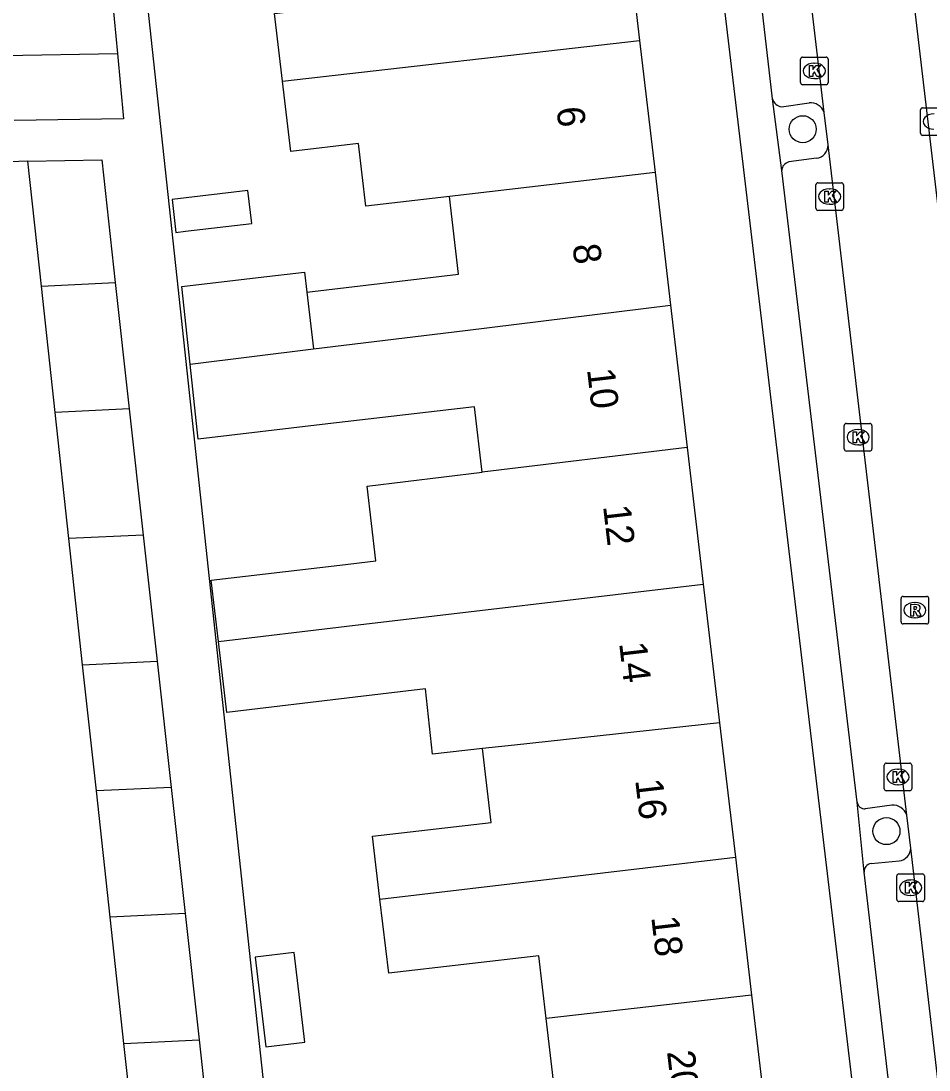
# Model space of a CAD drawing. Extents: x 162250 to 162654, y 380744 to 381605.
# Drawn here: x 162420.44 to 162453.35, y 381062.24 to 381100.24 of the extents above; entities that cross this region are included whole.
import ezdxf

# ---------------------------------------------------------------- set-up
doc = ezdxf.new("R2010")
doc.units = 0
for name, color, linetype in [('IMGEO_Boom', 7, 'Continuous'), ('IMGEO_Kolk', 7, 'Continuous'), ('IMGEO_Pand', 7, 'Continuous'), ('IMGEO_Pand_nummerreeks', 7, 'Continuous'), ('IMGEO_Parkeervlak_open', 7, 'Continuous'), ('IMGEO_Rijbaan_lokaal_open', 7, 'Continuous'), ('IMGEO_Rioolput', 7, 'Continuous'), ('IMGEO_Voetpad_open', 7, 'Continuous')]:
    doc.layers.add(name, color=color, linetype=linetype)

msp = doc.modelspace()

# ---------------------------------------------------------------- linework, layer by layer
at = {"layer": 'IMGEO_Boom'}
for centre in [(162448.769, 381096.32), (162451.803, 381070.891)]:
    msp.add_circle(centre, 0.489, dxfattribs=at)
at = {"layer": 'IMGEO_Kolk'}
for p, q in [((162448.687, 381098.007), (162448.687, 381098.859)), ((162448.762, 381098.933), (162449.614, 381098.933)), ((162449.175, 381098.713), (162449.2, 381098.713)), ((162449.688, 381098.859), (162449.688, 381098.007)), ((162449.614, 381097.933), (162448.762, 381097.933)), ((162449.198, 381098.153), (162449.173, 381098.153)), ((162453.037, 381096.172), (162453.037, 381097.024)), ((162453.112, 381097.098), (162453.964, 381097.098)), ((162453.964, 381096.098), (162453.112, 381096.098)), ((162449.243, 381093.455), (162449.243, 381094.307)), ((162449.318, 381094.381), (162450.17, 381094.381)), ((162449.731, 381094.161), (162449.756, 381094.161)), ((162450.244, 381094.307), (162450.244, 381093.455)), ((162450.17, 381093.381), (162449.318, 381093.381)), ((162449.754, 381093.601), (162449.729, 381093.601)), ((162450.274, 381084.736), (162450.274, 381085.588)), ((162450.349, 381085.662), (162451.201, 381085.662)), ((162450.762, 381085.442), (162450.787, 381085.442)), ((162451.275, 381085.588), (162451.275, 381084.736)), ((162451.201, 381084.662), (162450.349, 381084.662)), ((162450.785, 381084.882), (162450.76, 381084.882)), ((162451.72, 381072.428), (162451.72, 381073.28)), ((162451.795, 381073.354), (162452.647, 381073.354)), ((162452.721, 381073.28), (162452.721, 381072.428)), ((162452.208, 381073.134), (162452.233, 381073.134)), ((162452.231, 381072.574), (162452.206, 381072.574)), ((162452.647, 381072.354), (162451.795, 381072.354)), ((162452.177, 381068.416), (162452.177, 381069.268)), ((162452.252, 381069.342), (162453.104, 381069.342)), ((162452.665, 381069.122), (162452.69, 381069.122)), ((162453.178, 381069.268), (162453.178, 381068.416)), ((162453.104, 381068.342), (162452.252, 381068.342)), ((162452.688, 381068.562), (162452.663, 381068.562))]:
    msp.add_line(p, q, dxfattribs=at)
for points in [[(162448.687, 381098.007), (162448.687, 381098.859)], [(162448.762, 381098.933), (162449.614, 381098.933)], [(162449.688, 381098.859), (162449.688, 381098.007)], [(162449.008, 381098.633), (162449.131, 381098.633), (162449.131, 381098.482), (162449.261, 381098.633), (162449.425, 381098.633), (162449.279, 381098.482), (162449.432, 381098.233), (162449.28, 381098.233), (162449.195, 381098.397), (162449.131, 381098.33), (162449.131, 381098.233), (162449.008, 381098.233), (162449.008, 381098.633)], [(162449.614, 381097.933), (162448.762, 381097.933)], [(162453.037, 381096.172), (162453.037, 381097.024)], [(162453.112, 381097.098), (162453.964, 381097.098)], [(162453.964, 381096.098), (162453.112, 381096.098)], [(162449.243, 381093.455), (162449.243, 381094.307)], [(162449.318, 381094.381), (162450.17, 381094.381)], [(162450.244, 381094.307), (162450.244, 381093.455)], [(162449.564, 381094.081), (162449.687, 381094.081), (162449.687, 381093.93), (162449.817, 381094.081), (162449.981, 381094.081), (162449.835, 381093.93), (162449.988, 381093.681), (162449.836, 381093.681), (162449.751, 381093.845), (162449.687, 381093.778), (162449.687, 381093.681), (162449.564, 381093.681), (162449.564, 381094.081)], [(162450.17, 381093.381), (162449.318, 381093.381)], [(162450.274, 381084.736), (162450.274, 381085.588)], [(162450.349, 381085.662), (162451.201, 381085.662)], [(162450.595, 381085.362), (162450.718, 381085.362), (162450.718, 381085.211), (162450.848, 381085.362), (162451.012, 381085.362), (162450.866, 381085.211), (162451.019, 381084.962), (162450.867, 381084.962), (162450.782, 381085.126), (162450.718, 381085.059), (162450.718, 381084.962), (162450.595, 381084.962), (162450.595, 381085.362)], [(162451.275, 381085.588), (162451.275, 381084.736)], [(162451.201, 381084.662), (162450.349, 381084.662)], [(162451.72, 381072.428), (162451.72, 381073.28)], [(162451.795, 381073.354), (162452.647, 381073.354)], [(162452.721, 381073.28), (162452.721, 381072.428)], [(162452.041, 381073.054), (162452.164, 381073.054), (162452.164, 381072.903), (162452.294, 381073.054), (162452.458, 381073.054), (162452.312, 381072.903), (162452.465, 381072.654), (162452.313, 381072.654), (162452.228, 381072.818), (162452.164, 381072.751), (162452.164, 381072.654), (162452.041, 381072.654), (162452.041, 381073.054)], [(162452.647, 381072.354), (162451.795, 381072.354)], [(162452.177, 381068.416), (162452.177, 381069.268)], [(162452.252, 381069.342), (162453.104, 381069.342)], [(162452.498, 381069.042), (162452.621, 381069.042), (162452.621, 381068.891), (162452.751, 381069.042), (162452.915, 381069.042), (162452.769, 381068.891), (162452.922, 381068.642), (162452.77, 381068.642), (162452.685, 381068.806), (162452.621, 381068.739), (162452.621, 381068.642), (162452.498, 381068.642), (162452.498, 381069.042)], [(162453.178, 381069.268), (162453.178, 381068.416)], [(162453.104, 381068.342), (162452.252, 381068.342)]]:
    msp.add_lwpolyline(points, dxfattribs=at)
for centre, start, end in [((162448.764, 381098.857), 91.552, 178.448), ((162448.764, 381098.857), 91.552, 178.448), ((162449.612, 381098.857), 1.552, 88.448), ((162449.612, 381098.857), 1.552, 88.448), ((162448.764, 381098.009), 181.552, 268.448), ((162448.764, 381098.009), 181.552, 268.448), ((162449.612, 381098.009), 271.552, 358.448), ((162449.612, 381098.009), 271.552, 358.448), ((162453.114, 381097.022), 91.552, 178.448), ((162453.114, 381097.022), 91.552, 178.448), ((162453.114, 381096.174), 181.552, 268.448), ((162453.114, 381096.174), 181.552, 268.448), ((162449.32, 381094.305), 91.552, 178.448), ((162449.32, 381094.305), 91.552, 178.448), ((162450.168, 381094.305), 1.552, 88.448), ((162450.168, 381094.305), 1.552, 88.448), ((162449.32, 381093.457), 181.552, 268.448), ((162449.32, 381093.457), 181.552, 268.448), ((162450.168, 381093.457), 271.552, 358.448), ((162450.168, 381093.457), 271.552, 358.448), ((162450.351, 381085.586), 91.552, 178.448), ((162450.351, 381085.586), 91.552, 178.448), ((162451.199, 381085.586), 1.552, 88.448), ((162451.199, 381085.586), 1.552, 88.448), ((162450.351, 381084.738), 181.552, 268.448), ((162450.351, 381084.738), 181.552, 268.448), ((162451.199, 381084.738), 271.552, 358.448), ((162451.199, 381084.738), 271.552, 358.448), ((162451.797, 381073.278), 91.552, 178.448), ((162451.797, 381073.278), 91.552, 178.448), ((162452.645, 381073.278), 1.552, 88.448), ((162452.645, 381073.278), 1.552, 88.448), ((162451.797, 381072.43), 181.552, 268.448), ((162451.797, 381072.43), 181.552, 268.448), ((162452.645, 381072.43), 271.552, 358.448), ((162452.645, 381072.43), 271.552, 358.448), ((162452.254, 381069.266), 91.552, 178.448), ((162452.254, 381069.266), 91.552, 178.448), ((162453.102, 381069.266), 1.552, 88.448), ((162453.102, 381069.266), 1.552, 88.448), ((162452.254, 381068.418), 181.552, 268.448), ((162452.254, 381068.418), 181.552, 268.448), ((162453.102, 381068.418), 271.552, 358.448), ((162453.102, 381068.418), 271.552, 358.448)]:
    msp.add_arc(centre, 0.0765, start, end, dxfattribs=at)
for centre, major_axis, ratio, start_param, end_param in [((162449.174, 381098.433), (-0.387, 0.002), 0.722429, 4.712389, 7.853982), ((162449.199, 381098.433), (-0.39, 0.002), 0.717154, 1.570796, 4.712389), ((162453.524, 381096.598), (-0.387, 0.002), 0.722429, 4.712389, 7.853982), ((162449.73, 381093.881), (-0.387, 0.002), 0.722429, 4.712389, 7.853982), ((162449.755, 381093.881), (-0.39, 0.002), 0.717154, 1.570796, 4.712389), ((162450.761, 381085.162), (-0.387, 0.002), 0.722429, 4.712389, 7.853982), ((162450.786, 381085.162), (-0.39, 0.002), 0.717154, 1.570796, 4.712389), ((162452.207, 381072.854), (-0.387, 0.002), 0.722429, 4.712389, 7.853982), ((162452.232, 381072.854), (-0.39, 0.002), 0.717154, 1.570796, 4.712389), ((162452.664, 381068.842), (-0.387, 0.002), 0.722429, 4.712389, 7.853982), ((162452.689, 381068.842), (-0.39, 0.002), 0.717154, 1.570796, 4.712389)]:
    msp.add_ellipse(centre, major_axis=major_axis, ratio=ratio, start_param=start_param, end_param=end_param, dxfattribs=at)
at = {"layer": 'IMGEO_Pand'}
for points in [[(162442.256, 381104.637), (162442.854, 381099.538)], [(162429.914, 381098.061), (162429.626, 381100.509), (162435.098, 381101.151), (162434.792, 381103.761)], [(162429.914, 381098.061), (162442.854, 381099.538)], [(162442.854, 381099.538), (162443.415, 381094.753)], [(162419.818, 381098.989), (162423.934, 381099.061)], [(162423.934, 381099.061), (162424.156, 381096.7), (162420.193, 381096.631)], [(162435.962, 381093.885), (162432.937, 381093.528), (162432.67, 381095.8), (162430.213, 381095.511), (162429.914, 381098.061)], [(162420.683, 381095.161), (162423.364, 381095.214), (162423.856, 381090.762)], [(162421.177, 381090.633), (162420.683, 381095.161)], [(162443.415, 381094.753), (162435.962, 381093.885)], [(162443.415, 381094.753), (162443.98, 381089.943)], [(162428.662, 381094.098), (162425.918, 381093.776), (162426.048, 381092.583), (162426.402, 381092.625), (162428.802, 381092.906), (162428.662, 381094.098)], [(162430.792, 381090.42), (162436.293, 381091.066), (162435.962, 381093.885)], [(162426.568, 381087.813), (162426.262, 381090.621), (162429.032, 381090.946), (162430.707, 381091.143), (162430.792, 381090.42)], [(162421.177, 381090.633), (162423.856, 381090.762)], [(162423.856, 381090.762), (162424.362, 381086.193)], [(162421.676, 381086.063), (162421.177, 381090.633)], [(162430.792, 381090.42), (162431.034, 381088.359)], [(162431.034, 381088.359), (162436.533, 381089.032), (162443.98, 381089.943)], [(162443.98, 381089.943), (162444.584, 381084.793)], [(162426.568, 381087.813), (162431.034, 381088.359)], [(162437.146, 381083.895), (162436.868, 381086.264), (162431.356, 381085.617), (162426.865, 381085.09), (162426.568, 381087.813)], [(162424.362, 381086.193), (162421.676, 381086.063)], [(162424.362, 381086.193), (162424.868, 381081.619)], [(162422.175, 381081.49), (162421.676, 381086.063)], [(162444.584, 381084.793), (162437.146, 381083.895)], [(162444.584, 381084.793), (162445.165, 381079.841)], [(162427.594, 381077.76), (162427.333, 381079.982), (162431.988, 381080.528), (162433.301, 381080.682), (162432.984, 381083.392), (162437.146, 381083.895)], [(162424.868, 381081.619), (162422.175, 381081.49)], [(162424.868, 381081.619), (162425.373, 381077.048)], [(162422.673, 381076.919), (162422.175, 381081.49)], [(162427.594, 381077.76), (162432.248, 381078.311), (162445.165, 381079.841)], [(162445.165, 381079.841), (162445.754, 381074.817)], [(162437.162, 381073.882), (162435.35, 381073.685), (162435.094, 381076.041), (162432.55, 381075.742), (162427.895, 381075.195), (162427.594, 381077.76)], [(162422.673, 381076.919), (162425.373, 381077.048)], [(162425.373, 381077.048), (162425.879, 381072.476)], [(162423.172, 381072.346), (162422.673, 381076.919)], [(162445.754, 381074.817), (162438.325, 381074.009), (162437.162, 381073.882)], [(162445.754, 381074.817), (162446.326, 381069.944)], [(162433.448, 381068.428), (162433.18, 381070.706), (162437.476, 381071.21), (162437.162, 381073.882)], [(162425.879, 381072.476), (162423.172, 381072.346)], [(162425.879, 381072.476), (162426.385, 381067.905)], [(162423.671, 381067.775), (162423.172, 381072.346)], [(162433.448, 381068.428), (162446.326, 381069.944)], [(162446.326, 381069.944), (162446.912, 381064.945)], [(162439.467, 381064.106), (162439.2, 381066.38), (162433.763, 381065.742), (162433.448, 381068.428)], [(162426.385, 381067.905), (162423.671, 381067.775)], [(162426.385, 381067.905), (162426.89, 381063.333)], [(162424.169, 381063.202), (162423.671, 381067.775)], [(162428.93, 381066.328), (162429.311, 381063.077), (162430.722, 381063.243), (162430.341, 381066.493), (162428.93, 381066.328)], [(162446.912, 381064.945), (162439.467, 381064.106)], [(162446.912, 381064.945), (162447.489, 381060.029)], [(162434.643, 381058.596), (162434.385, 381060.793), (162439.781, 381061.426), (162439.467, 381064.106)], [(162424.169, 381063.202), (162426.89, 381063.333)], [(162426.89, 381063.333), (162427.396, 381058.762)], [(162424.668, 381058.631), (162424.169, 381063.202)]]:
    msp.add_lwpolyline(points, dxfattribs=at)
at = {"layer": 'IMGEO_Parkeervlak_open'}
for points in [[(162448, 381097.131), (162449.002, 381097.274)], [(162449.268, 381095.266), (162448.264, 381095.132)], [(162451.998, 381071.83), (162451.034, 381071.697)], [(162451.248, 381069.716), (162452.262, 381069.813)]]:
    msp.add_lwpolyline(points, dxfattribs=at)
for centre, radius, start, end in [((162448.049, 381097.518), 0.391, 194.7572, 262.8463), ((162449.053, 381096.76), 0.516, 18.7367, 95.6642), ((162449.189, 381095.759), 0.5, 279.0424, 358.8044), ((162448.33, 381094.821), 0.318, 102.0465, 180.0984), ((162451.023, 381071.987), 0.29, 189.29, 272.1312), ((162452.039, 381071.303), 0.529, 19.0046, 94.4502), ((162452.191, 381070.307), 0.499, 278.1746, 356.9491), ((162451.278, 381069.433), 0.285, 95.9638, 184.8301)]:
    msp.add_arc(centre, radius, start, end, dxfattribs=at)
at = {"layer": 'IMGEO_Rijbaan_lokaal_open'}
for points in [[(162449.542, 381096.926), (162446.81, 381120.142)], [(162451.771, 381109.645), (162454.497, 381086.417)], [(162449.689, 381095.749), (162449.542, 381096.926)], [(162452.539, 381071.475), (162449.689, 381095.749)], [(162452.689, 381070.28), (162452.539, 381071.475)], [(162455.466, 381046.471), (162452.689, 381070.28)]]:
    msp.add_lwpolyline(points, dxfattribs=at)
at = {"layer": 'IMGEO_Rioolput'}
for p, q in [((162452.331, 381078.47), (162452.331, 381079.322)), ((162452.406, 381079.396), (162453.258, 381079.396)), ((162453.332, 381079.322), (162453.332, 381078.47)), ((162452.819, 381079.176), (162452.844, 381079.176)), ((162452.842, 381078.616), (162452.817, 381078.616)), ((162453.258, 381078.396), (162452.406, 381078.396))]:
    msp.add_line(p, q, dxfattribs=at)
for points in [[(162452.331, 381078.47), (162452.331, 381079.322)], [(162452.406, 381079.396), (162453.258, 381079.396)], [(162453.332, 381079.322), (162453.332, 381078.47)], [(162452.92, 381079.094), (162452.668, 381079.096), (162452.668, 381078.696)], [(162452.846, 381079.015), (162452.792, 381079.015), (162452.792, 381078.934)], [(162452.792, 381078.934), (162452.844, 381078.934)], [(162452.668, 381078.696), (162452.792, 381078.696), (162452.792, 381078.858), (162452.803, 381078.858)], [(162452.85, 381078.829), (162452.921, 381078.696), (162453.061, 381078.696), (162452.996, 381078.822)], [(162453.258, 381078.396), (162452.406, 381078.396)]]:
    msp.add_lwpolyline(points, dxfattribs=at)
for centre, radius, start, end in [((162452.408, 381079.32), 0.0765, 91.552, 178.448), ((162452.408, 381079.32), 0.0765, 91.552, 178.448), ((162453.256, 381079.32), 0.0765, 1.552, 88.448), ((162453.256, 381079.32), 0.0765, 1.552, 88.448), ((162452.828, 381079.123), 0.19, 274.7715, 282.9687), ((162452.852, 381078.919), 0.0964, 77.0061, 93.1865), ((162452.866, 381078.976), 0.0378, 276.6634, 79.6772), ((162452.919, 381078.984), 0.109, 350.3612, 89.416), ((162452.917, 381078.984), 0.112, 277.5842, 350.9817), ((162452.802, 381078.805), 0.0533, 26.0293, 88.6989), ((162452.901, 381078.769), 0.108, 29.5134, 73.7905), ((162452.408, 381078.472), 0.0765, 181.552, 268.448), ((162452.408, 381078.472), 0.0765, 181.552, 268.448), ((162453.256, 381078.472), 0.0765, 271.552, 358.448), ((162453.256, 381078.472), 0.0765, 271.552, 358.448)]:
    msp.add_arc(centre, radius, start, end, dxfattribs=at)
for centre, major_axis, ratio, start_param, end_param in [((162452.818, 381078.896), (-0.387, 0.002), 0.722429, 4.712389, 7.853982), ((162452.843, 381078.896), (-0.39, 0.002), 0.717154, 1.570796, 4.712389)]:
    msp.add_ellipse(centre, major_axis=major_axis, ratio=ratio, start_param=start_param, end_param=end_param, dxfattribs=at)
at = {"layer": 'IMGEO_Voetpad_open'}
for points in [[(162447.671, 381097.419), (162445.147, 381119.325)], [(162436.213, 381104.992), (162423.638, 381102.209), (162423.934, 381099.061)], [(162460.106, 380980.583), (162457.834, 381000), (162450.879, 381059.205), (162445.423, 381105.014)], [(162429.65, 381057.925), (162426.098, 381090.941), (162424.979, 381101.344), (162434.792, 381103.761)], [(162448.012, 381094.82), (162447.671, 381097.419)], [(162420.683, 381095.161), (162412.421, 381094.865)], [(162450.737, 381071.94), (162448.012, 381094.82)], [(162450.994, 381069.409), (162450.737, 381071.94)], [(162453.668, 381046.538), (162450.994, 381069.409)]]:
    msp.add_lwpolyline(points, dxfattribs=at)

# ---------------------------------------------------------------- texts
at = {"layer": 'IMGEO_Pand_nummerreeks'}
for s, rotation, p in [('6', 276.6919, (162439.84, 381097.087)), ('8', 276.6919, (162440.423, 381092.122)), ('10', 276.6919, (162440.949, 381087.619)), ('12', 276.6919, (162441.53, 381082.664)), ('14', 276.6919, (162442.113, 381077.7)), ('16', 276.6903, (162442.695, 381072.741)), ('18', 276.6903, (162443.277, 381067.777)), ('20', 276.6903, (162443.848, 381062.906))]:
    msp.add_text(s, height=1, rotation=rotation, dxfattribs=at).set_placement(p)

doc.saveas('drawing.dxf')
